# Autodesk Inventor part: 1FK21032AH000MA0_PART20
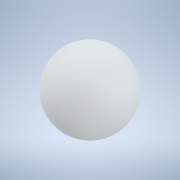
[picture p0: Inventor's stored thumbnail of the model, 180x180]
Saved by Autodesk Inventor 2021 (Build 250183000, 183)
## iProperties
Created: 2025-04
Part Number: 1FK21032AH000MA0_PART20
Material: Generic
Catalog Web Link: www.3dfindit.com
Description: -Servo synchronous motor
Document SubType Name: Modeling
Designer: psAdmin
Mass: 0.113097 g
Surface Area: 1.13097 cm^2
Volume: 0.113097 cm^3
Density: 1 g/cm^3
Appearance: PSOLRGB-212-217-219
Category: PARTsolutions
Title: 1FK21032AH000MA0_PART20
Author: Cadenas PARTsolutions
Comments: Servo synchronous motor
Sending System: PARTsolutions
Preprocessor: ST-DEVELOPER v19.3
PSOL_IDENT_0: {$CADENAS_DATA/23d-libs/siemens_ag/_cat_/45/10/1fk21032ah000ma0.prj},216 {VTYP=3D},{NB=1FK21032AH000
PSOL_IDENT_1: MA0_PART20},{LINA=1FK21032AH000MA0_PART20},{NN=1FK21032AH000MA0_PART20},{NOPRJ=TRUE},{DATE=19.08.202
PSOL_IDENT_2: 5 14:00:35},{GEOMDATE=30.07.2025 02:02:03},{VERSION=},{LINEID=10},{WBVAR=},{WBNUMERIC=}  {NB=1FK2103
PSOL_IDENT_3: 2AH000MA0_PART20},{LINA=1FK21032AH000MA0_PART20},{KT=DUMMY},{PREVIEW=../../../_pool_/14/8e/p_d211_xx
PSOL_IDENT_4: _00426j.png},{DESCSHORT=SIMOTICS S-1FK2 HD, SINAMICS S210 3AC 400V-480V, 0.59 Nm, 4500 rpm},{DESCLON
PSOL_IDENT_5: G=SIMOTICS S-1FK2 HD servo motor M0=0.64 Nm; PN = 0.28 kW at nN=4500 rpm (380-480 V); PN = 0.167 kW
PSOL_IDENT_6: at nN=2500 rpm (200-240 V); degree of protection IP64; cylindrical shaft D14 x 30 mm; absolute encod
PSOL_IDENT_7: er 22-bit + 12-bit multiturn (encoder AM22DQC); with OCC interface; plug size M17, rotatable; SIMOTI
PSOL_IDENT_8: CS S-1FK2 servomotorfor a wide range of uses in industrial environments. SIMOTICS S‑1FK2 servomotors
PSOL_IDENT_9: are compact synchronous motors with a high dynamic performance that set themselves apart as a resul
PSOL_IDENT_10: t of their high power density, degree of protection and overload capability. The motors are availabl
PSOL_IDENT_11: e in two variants: as High Dynamic variant (highest dynamic performance as a result of the low intri
PSOL_IDENT_12: nsic moment of inertia for applications demanding a high dynamic performance with low moved masses)
PSOL_IDENT_13: - and as Compact variant (precise and stable closed-loop control for medium up to large moved masses
PSOL_IDENT_14: as a result of a medium intrinsic moment of inertia). SIMOTICSS‑1FK2 servomotors fully exploit thei
PSOL_IDENT_15: r strengths in a system with the SINAMICSS210 frequency converter and simple connection using the on
PSOL_IDENT_16: e cable connection (OCC). Advantages include the short control and positioning times, fast and preci
PSOL_IDENT_17: se correction of disturbing quantities as well as stable control with a high dynamic performance. Th
PSOL_IDENT_18: e servo motors can be configured to address a wide range of requirements. For example with and witho
PSOL_IDENT_19: ut holding brake, IP64 or IP65 degree of protection, singleturn or multiturn absolute encoders - to
PSOL_IDENT_20: name just a few. Further, the servomotors are available in different shaft heights extending from 20
PSOL_IDENT_21: to 100. A shaft sealing ring is available to achieve an IP65 degree of protection and for subsequen
PSOL_IDENT_22: t mounting at the motor or as spare part. SIMOTICS - the optimum motor for each and every motion con
PSOL_IDENT_23: trol application.},{INTNO=195125335004},{SUPPLIERALTNO=1FK2103-2AH00-0MA0},{MANUID=1FK21032AH000MA0}
PSOL_IDENT_24: ,{MANUNAME=Siemens},{MANUTYPEDESC=SYNCHRONOUS MOTOR 1FK2 HD 0,64 NM},{AAU732=SIMOTICS},{AAO057=S-1FK
PSOL_IDENT_25: 2},{AAU734=SIMOTICS S-1FK2 HD servo motor M0=0.64 Nm; PN = 0.28 kW at nN=4500 rpm (380-480 V); PN =
PSOL_IDENT_26: 0.167 kW at nN=2500 rpm (200-240 V); degree of protection IP64; cylindrical shaft D14 x 30 mm; absol
PSOL_IDENT_27: ute encoder 22-bit + 12-bit multiturn (encoder AM22DQC); with OCC interface; plug size M17, rotatabl
PSOL_IDENT_28: e;},{AAW338=SYNCHRONOUS MOTOR 1FK2 HD 0,64 NM},{AAO742=SIMOTICS},{AAO663=4034106444624},{NOCUPEROU=1
PSOL_IDENT_29: },{PRICEQUANTITY=1},{QUANTITYMIN=1},{QUANTITYINT=1},{CTN=85015100},{COO=RO},{AAO676=1FK2103-2AH00-0M
PSOL_IDENT_30: A0},{AAO677=Siemens AG},{ORDERUNIT=C62},{CONTENTUNIT=C62}
NB: 1FK21032AH000MA0_PART20
NT: Servo synchronous motor
NBSYN: $MANUID._PART20
LINA: 1FK21032AH000MA0_PART20
CATALOG: SIEMENS
PREVIEW: ../../../_pool_/14/8e/p_d211_xx_00426j.png
DESCSHORT: SIMOTICS S-1FK2 HD, SINAMICS S210 3AC 400V-480V, 0.59 Nm, 4500 rpm
DESCLONG: SIMOTICS S-1FK2 HD servo motor M0=0.64 Nm; PN = 0.28 kW at nN=4500 rpm (380-480 V); PN = 0.167 kW at nN=2500 rpm (200-240 V); degree of protection IP64; cylindr
INTNO: 195125335004
SUPPLIERALTNO: 1FK2103-2AH00-0MA0
MANUID: 1FK21032AH000MA0
MANUNAME: Siemens
MANUTYPEDESC: SYNCHRONOUS MOTOR 1FK2 HD 0,64 NM
AAU732: SIMOTICS
AAO057: S-1FK2
AAU734: SIMOTICS S-1FK2 HD servo motor M0=0.64 Nm; PN = 0.28 kW at nN=4500 rpm (380-480 V); PN = 0.167 kW at nN=2500 rpm (200-240 V); degree of protection IP64; cylindr
AAW338: SYNCHRONOUS MOTOR 1FK2 HD 0,64 NM
AAO742: SIMOTICS
AAO663: 4034106444624.0
NOCUPEROU: 1
PRICEQUANTITY: 1
QUANTITYMIN: 1
QUANTITYINT: 1
CTN: 85015100
COO: RO
ARTICLENO: 1FK21032AH000MA0_PART20
BOMINFO: 1FK21032AH000MA0_PART20
CREATOR: CADENAS GmbH
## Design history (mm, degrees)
feature "2025_04_17_15_00_20_0760"
body "Solid1"
